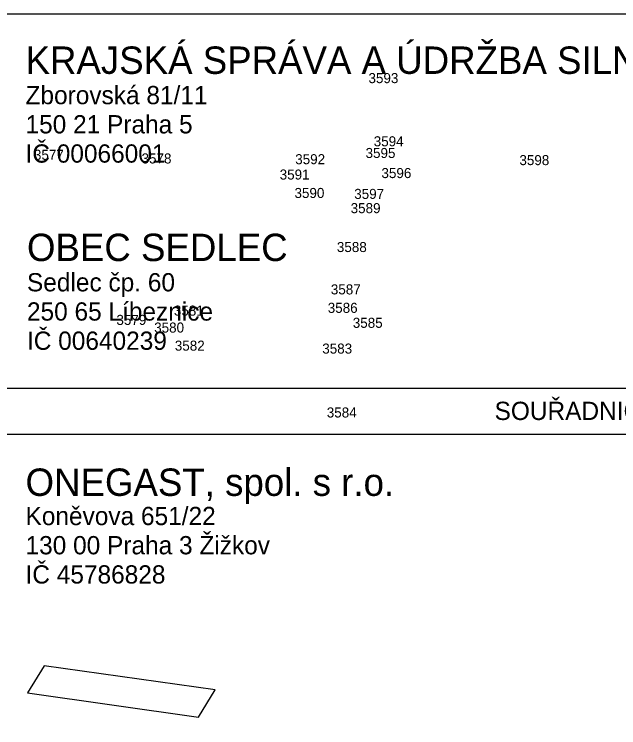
# Model space of a CAD drawing. Extents: x -740053 to -737517, y -1033516 to -1032476.
# Drawn here: x -739059.3 to -739026.22, y -1032591.95 to -1032552.88 of the extents above; entities that cross this region are included whole.
import ezdxf

# ---------------------------------------------------------------- set-up
doc = ezdxf.new("R2010")
doc.units = 0
for name, color, linetype in [('bod-cislo', 7, 'Continuous'), ('bod-oznac', 7, 'Continuous'), ('promika-rozp', 7, 'Continuous'), ('promika-rozp-text', 7, 'Continuous'), ('promika-rozp-text-firmy', 7, 'Continuous'), ('Vrstva 1', 7, 'Continuous')]:
    doc.layers.add(name, color=color, linetype=linetype)

# ---------------------------------------------------------------- blocks, each defined once
blk = doc.blocks.new('POINT_DISPLAY')
blk.add_line((0, 0), (0, 0))

msp = doc.modelspace()

# ---------------------------------------------------------------- linework, layer by layer
at = {"layer": 'promika-rozp'}
for points in [[(-739001.385, -1032563.132), (-739001.385, -1032552.882), (-739091.385, -1032552.882), (-739091.385, -1032563.132)], [(-739001.385, -1032563.132), (-739001.385, -1032573.382), (-739091.385, -1032573.382), (-739091.385, -1032563.132)], [(-739091.385, -1032596.382), (-739091.385, -1032575.882), (-739001.385, -1032575.882), (-739001.385, -1032596.382)]]:
    msp.add_lwpolyline(points, dxfattribs=at)
at = {"layer": 'Vrstva 1'}
msp.add_lwpolyline([(-739058.575, -1032590.04), (-739049.214, -1032591.367), (-739048.311, -1032589.884), (-739057.672, -1032588.557)], close=True, dxfattribs=at)

# ---------------------------------------------------------------- block references
at = {"layer": 'bod-oznac'}
msp.add_blockref('POINT_DISPLAY', (-739045.852, -1032554.407), dxfattribs=at)

# ---------------------------------------------------------------- texts
at = {"layer": 'bod-cislo'}
for s, p in [('3593', (-739039.918, -1032556.653)), ('3594', (-739039.631, -1032560.113)), ('3577', (-739058.228, -1032560.853)), ('3595', (-739040.078, -1032560.753)), ('3578', (-739052.338, -1032561.053)), ('3592', (-739043.928, -1032561.093)), ('3598', (-739031.658, -1032561.143)), ('3591', (-739044.779, -1032561.933)), ('3596', (-739039.208, -1032561.853)), ('3590', (-739043.968, -1032562.943)), ('3597', (-739040.698, -1032562.993)), ('3589', (-739040.895, -1032563.773)), ('3588', (-739041.648, -1032565.903)), ('3587', (-739041.978, -1032568.223)), ('3581', (-739050.569, -1032569.383)), ('3586', (-739042.148, -1032569.233)), ('3579', (-739053.715, -1032569.893)), ('3580', (-739051.648, -1032570.313)), ('3585', (-739040.778, -1032570.053)), ('3582', (-739050.518, -1032571.303)), ('3583', (-739042.448, -1032571.463)), ('3584', (-739042.201, -1032574.963))]:
    msp.add_text(s, height=0.55, dxfattribs=at).set_placement(p)
at = {"layer": 'promika-rozp'}
msp.add_text('SOUŘADNICOVÝ SYSTÉM S-JTSK  VÝŠKOVÝ SYSTÉM Bpv', height=1, dxfattribs=at).set_placement((-739033.017, -1032575.1))
at = {"layer": 'promika-rozp-text'}
for s, height, p in [('ONEGAST, spol. s r.o.', 1.5, (-739058.689, -1032579.256)), ('Koněvova 651/22', 1, (-739058.689, -1032580.856)), ('130 00 Praha 3 Žižkov', 1, (-739058.689, -1032582.456)), ('IČ 45786828', 1, (-739058.689, -1032584.056))]:
    msp.add_text(s, height=height, dxfattribs=at).set_placement(p)
at = {"layer": 'promika-rozp-text-firmy'}
for s, height, p in [('KRAJSKÁ SPRÁVA A ÚDRŽBA SILNIC STŘEDOČESKÉHO KRAJE, P.O.', 1.5, (-739058.689, -1032556.147)), ('Zborovská 81/11', 1, (-739058.689, -1032557.807)), ('150 21 Praha 5', 1, (-739058.689, -1032559.407)), ('IČ 00066001', 1, (-739058.689, -1032561.007)), ('OBEC SEDLEC', 1.5, (-739058.61, -1032566.397)), ('Sedlec čp. 60', 1, (-739058.61, -1032568.057)), ('250 65 Líbeznice', 1, (-739058.61, -1032569.657)), ('IČ 00640239', 1, (-739058.61, -1032571.257))]:
    msp.add_text(s, height=height, dxfattribs=at).set_placement(p)

doc.saveas('drawing.dxf')
